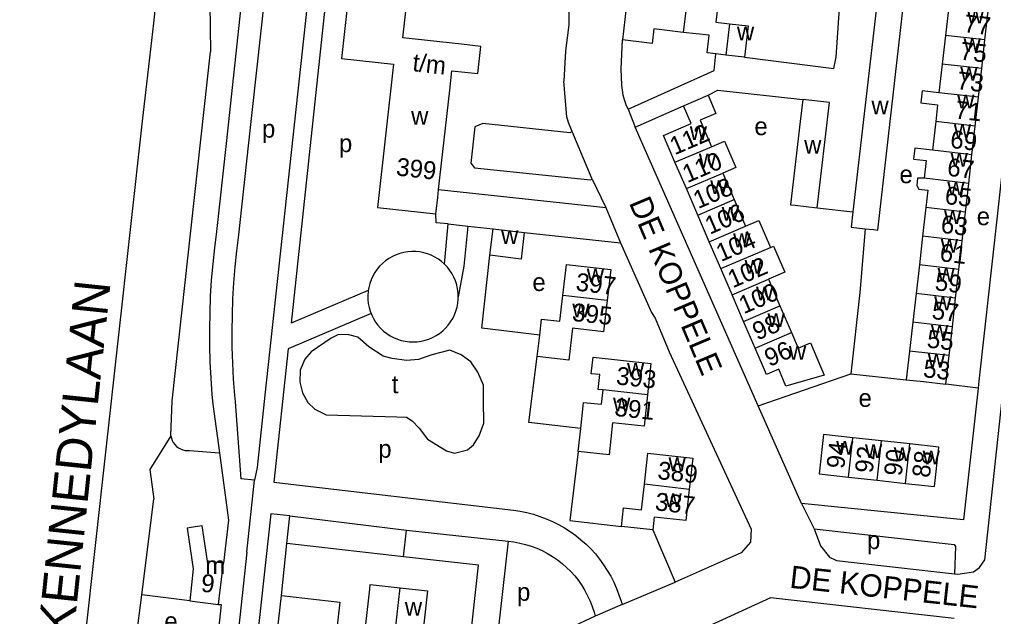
# Model space of a CAD drawing. Extents: x 161936 to 163647, y 386450 to 388633.
# Drawn here: x 162068.8 to 162286.5, y 387817.5 to 387951 of the extents above; entities that cross this region are included whole.
import ezdxf

# ---------------------------------------------------------------- set-up
doc = ezdxf.new("R2010")
doc.units = 0
for name, color, linetype in [('BLT_Basislijn', 7, 'Continuous'), ('BLT_Bebouwing', 7, 'Continuous'), ('BLT_Centroide', 7, 'Continuous'), ('BLT_Huisnummer', 7, 'Continuous'), ('BLT_Huisnummer_ tussenligend', 7, 'Continuous'), ('BLT_Huisnummer_reeks', 7, 'Continuous'), ('BLT_Onderverdeling_panden', 7, 'Continuous'), ('BLT_Straatnaam', 7, 'Continuous'), ('BLT_Straatnaam_hoofdweg', 7, 'Continuous'), ('BLT_Vlakafsluiter', 7, 'Continuous')]:
    doc.layers.add(name, color=color, linetype=linetype)

msp = doc.modelspace()

# ---------------------------------------------------------------- linework, layer by layer
at = {"layer": 'BLT_Basislijn'}
for p, q in [((162126.83, 388032.86), (162114.95, 387923.3)), ((162128.74, 388003.15), (162119.92, 387922.75)), ((162191.53, 387954.4), (162191.53, 387949.81)), ((162191.53, 387949.81), (162190.84, 387944.01)), ((162203.22, 387939.99), (162203.56, 387946.44)), ((162102.93, 387865.74), (162111.5, 387943.8)), ((162190.84, 387944.01), (162190.41, 387937.21)), ((162204.78, 387930.94), (162206.35, 387926.93)), ((162096.24, 387928.96), (162087.98, 387854.23)), ((162192.32, 387925.95), (162191.47, 387927.99)), ((162196.79, 387915.34), (162192.32, 387925.95)), ((162233.88, 387864.59), (162206.35, 387926.93)), ((162114.95, 387923.3), (162112.8, 387903.59)), ((162119.92, 387922.75), (162117.74, 387902.85)), ((162196.79, 387915.34), (162199.8, 387908.98)), ((162162.44, 387913), (162199.8, 387908.98)), ((162199.8, 387908.98), (162203.11, 387901.11)), ((162247.09, 387908.88), (162255.03, 387907.99)), ((162163.75, 387896.31), (162164.6, 387905.29)), ((162164.6, 387905.29), (162168.97, 387904.82)), ((162168.97, 387904.82), (162174.62, 387904.21)), ((162181.6, 387903.36), (162203.11, 387901.11)), ((162146.73, 387890.41), (162129.46, 387883.07)), ((162147.37, 387885.25), (162128.85, 387877.38)), ((162233.88, 387864.59), (162254.59, 387871.78)), ((162254.59, 387871.78), (162266.98, 387870.47)), ((162283.04, 387868.59), (162275.81, 387869.47)), ((162102.63, 387857.93), (162102.93, 387865.74)), ((162111.98, 387865.02), (162113.47, 387854.09)), ((162116.96, 387865.48), (162118.26, 387848.26)), ((162243.57, 387842.75), (162233.88, 387864.59)), ((162087.98, 387854.23), (162079.71, 387778.65)), ((162106.76, 387854.65), (162113.47, 387854.09)), ((162097.94, 387850.35), (162098.81, 387843.78)), ((162121.3, 387847.99), (162118.26, 387848.26)), ((162119.61, 387831.87), (162121.3, 387847.99)), ((162096.12, 387822.38), (162098.81, 387843.78)), ((162243.57, 387842.75), (162246.4, 387837.14)), ((162128.56, 387833.82), (162129.22, 387840.05)), ((162129.22, 387840.05), (162155.27, 387836.85)), ((162210.32, 387836.86), (162215.32, 387825.2)), ((162127.32, 387822.18), (162128.56, 387833.82)), ((162154.6, 387830.84), (162128.56, 387833.82)), ((162119.61, 387831.87), (162116.25, 387801.31)), ((162203.44, 387820.16), (162215.32, 387825.2)), ((162094.34, 387808.2), (162096.12, 387822.38)), ((162106.85, 387821.03), (162096.12, 387822.38)), ((162113.85, 387820.16), (162112.26, 387805.95)), ((162113.27, 387820.22), (162113.85, 387820.16)), ((162203.44, 387820.16), (162197.42, 387817.55))]:
    msp.add_line(p, q, dxfattribs=at)
for points in [[(162118.49, 388036.48), (162111.07, 387970.73), (162111.5, 387943.8)], [(162106.41, 388028.03), (162105.03, 388012.45), (162103.57, 387996.88), (162102.02, 387981.32), (162100.4, 387965.76), (162098.7, 387950.21), (162096.92, 387934.67), (162096.24, 387928.96)], [(162128.74, 388003.15), (162137.41, 388002.59), (162138.21, 388001.69), (162123.63, 387867.04)], [(162147.41, 388001.2), (162142.14, 388001.69), (162129.46, 387883.07)], [(162277.73, 387827.08), (162278.49, 387826.95), (162282, 387827.52), (162283.32, 387828.45), (162284.5, 387830.2), (162299.98, 387972.98), (162299.82, 387975.12), (162297.88, 387978.05), (162295.24, 387978.68)], [(162230.8, 387942.6), (162250.79, 387940.04), (162251.3, 387942.58), (162252.07, 387953.52)], [(162292.27, 387952.1), (162283.13, 387869.44), (162283.04, 387868.59)], [(162204.78, 387930.94), (162224.01, 387939.65), (162224.42, 387943.34)], [(162204.78, 387930.94), (162204.35, 387931.97), (162204, 387933.03), (162203.72, 387934.11), (162203.52, 387935.21), (162203.4, 387936.32), (162203.22, 387939.99)], [(162191.47, 387927.99), (162191.1, 387929.24), (162190.41, 387937.21)], [(162222.7, 387934.07), (162224.88, 387935.22), (162243.85, 387933.15)], [(162206.35, 387926.93), (162217.18, 387931.7)], [(162192.32, 387925.95), (162191.77, 387925.71), (162172.35, 387927.79), (162170.55, 387927.03), (162169.65, 387918.86), (162170.5, 387917.81), (162196.42, 387915.13), (162196.79, 387915.34)], [(162164.6, 387905.29), (162161.87, 387905.58), (162161.83, 387907.55)], [(162168.97, 387904.82), (162168.08, 387895.89), (162166.85, 387889.02)], [(162257.77, 387904.23), (162256.6, 387890), (162254.59, 387871.78)], [(162112.8, 387903.59), (162112.34, 387899.97), (162111.96, 387896.34), (162111.65, 387892.7), (162111.43, 387889.05), (162111.29, 387885.41), (162111.23, 387881.75), (162111.25, 387878.1), (162111.35, 387874.45), (162111.53, 387870.8), (162111.79, 387867.16), (162111.98, 387865.02)], [(162117.74, 387902.85), (162117.29, 387899.29), (162116.92, 387895.71), (162116.63, 387892.12), (162116.41, 387888.53), (162116.28, 387884.94), (162116.23, 387881.34), (162116.26, 387877.74), (162116.37, 387874.15), (162116.55, 387870.56), (162116.82, 387866.97), (162116.96, 387865.48)], [(162203.11, 387901.11), (162210.02, 387885.52), (162210.87, 387884.19), (162213.99, 387876.67), (162232.29, 387837.04), (162232.13, 387834.11), (162230.06, 387831.72), (162215.32, 387825.2)], [(162163.75, 387896.31), (162163.11, 387896.88), (162162.39, 387897.41), (162161.62, 387897.88), (162160.81, 387898.28), (162159.97, 387898.61), (162159.11, 387898.86), (162158.23, 387899.03), (162157.33, 387899.12), (162156.43, 387899.13), (162155.54, 387899.07), (162154.65, 387898.92), (162153.78, 387898.69), (162152.93, 387898.39), (162152.11, 387898.02), (162151.33, 387897.57), (162150.6, 387897.06), (162149.91, 387896.48), (162149.27, 387895.84), (162148.69, 387895.15), (162148.18, 387894.41), (162147.74, 387893.63), (162147.36, 387892.82), (162147.06, 387891.97), (162146.84, 387891.1), (162146.73, 387890.41)], [(162185.06, 387880.4), (162172.09, 387881.96), (162173.9, 387898.28)], [(162166.85, 387889.02), (162166.81, 387889.92), (162166.69, 387890.81), (162166.49, 387891.69), (162166.22, 387892.55), (162165.87, 387893.37), (162165.45, 387894.17), (162164.96, 387894.92), (162164.4, 387895.63), (162163.75, 387896.31)], [(162146.73, 387890.41), (162146.7, 387890.21), (162146.63, 387889.31), (162146.64, 387888.41), (162146.74, 387887.52), (162146.91, 387886.64), (162147.16, 387885.77), (162147.37, 387885.25)], [(162147.37, 387885.25), (162147.49, 387884.93), (162147.89, 387884.13), (162148.36, 387883.36), (162148.89, 387882.64), (162149.49, 387881.97), (162150.15, 387881.35), (162150.86, 387880.8), (162151.61, 387880.31), (162152.4, 387879.89), (162153.23, 387879.54), (162154.09, 387879.26), (162154.97, 387879.07), (162155.86, 387878.95), (162156.76, 387878.91), (162157.65, 387878.95), (162158.55, 387879.07), (162159.42, 387879.27), (162160.28, 387879.55), (162161.11, 387879.9), (162161.9, 387880.32), (162162.65, 387880.82), (162163.36, 387881.37), (162164.01, 387881.99), (162164.61, 387882.67), (162165.14, 387883.39), (162165.61, 387884.16), (162166, 387884.97), (162166.33, 387885.8), (162166.58, 387886.67), (162166.74, 387887.55), (162166.84, 387888.45), (162166.85, 387889.02)], [(162128.85, 387877.38), (162125.66, 387847.58), (162179.21, 387841.26)], [(162194.22, 387859.54), (162182.61, 387860.91), (162184.49, 387875.64)], [(162123.63, 387867.04), (162121.92, 387850.83), (162121.3, 387847.99)], [(162283.04, 387868.59), (162279.75, 387839.13), (162243.57, 387842.75)], [(162102.63, 387857.93), (162102.73, 387857.39), (162102.91, 387856.88), (162103.16, 387856.39), (162103.48, 387855.95), (162103.85, 387855.56), (162104.29, 387855.23), (162104.76, 387854.97), (162105.27, 387854.77), (162105.81, 387854.66), (162106.35, 387854.62), (162106.76, 387854.65)], [(162113.47, 387854.09), (162115.52, 387839.07), (162114.34, 387829.46)], [(162193.67, 387854.43), (162191.8, 387839.01), (162203.31, 387837.65)], [(162179.21, 387841.26), (162180.71, 387841.04), (162182.19, 387840.74), (162183.66, 387840.36), (162185.1, 387839.9), (162186.52, 387839.37), (162187.91, 387838.76), (162189.26, 387838.08), (162190.58, 387837.33), (162191.85, 387836.52), (162193.08, 387835.63), (162194.26, 387834.68), (162195.39, 387833.68), (162196.46, 387832.61), (162197.48, 387831.49), (162198.44, 387830.31), (162199.33, 387829.09), (162200.15, 387827.82), (162200.91, 387826.51), (162201.6, 387825.16), (162202.22, 387823.78), (162202.76, 387822.37), (162203.23, 387820.93), (162203.44, 387820.16)], [(162129.22, 387840.05), (162124.98, 387840.43), (162111.62, 387718.53)], [(162246.4, 387837.14), (162247.83, 387833.3), (162249.81, 387830.75), (162251.36, 387830.05), (162277.73, 387827.08)], [(162246.4, 387837.14), (162277.65, 387833.63), (162278, 387833.19), (162277.73, 387827.08)], [(162177.97, 387834.33), (162179.29, 387834.17), (162180.59, 387833.94), (162181.88, 387833.63), (162183.15, 387833.24), (162184.39, 387832.77), (162185.6, 387832.23), (162186.78, 387831.62), (162187.91, 387830.94), (162189.01, 387830.19), (162190.05, 387829.38), (162191.05, 387828.5), (162191.99, 387827.57), (162192.87, 387826.58), (162193.7, 387825.54), (162194.45, 387824.45), (162195.14, 387823.32), (162195.76, 387822.15), (162196.31, 387820.95), (162196.79, 387819.71), (162197.19, 387818.44), (162197.42, 387817.55)], [(162173.46, 387793.42), (162145.03, 387796.5), (162144.11, 387797.49), (162147.05, 387823.63), (162147.16, 387824.69), (162153.83, 387823.94)], [(162277.67, 387817.03), (162236.65, 387821.68), (162194.65, 387802.43), (162190.57, 387799.23), (162189.04, 387797.32), (162187.24, 387793.74), (162185.17, 387773.27), (162186.7, 387769.43)], [(162197.42, 387817.55), (162185.65, 387812.09), (162181, 387808.08), (162178.67, 387805.4), (162177.72, 387804.96), (162174.66, 387804.5)]]:
    msp.add_lwpolyline(points, dxfattribs=at)
msp.add_lwpolyline([(162152.1, 387875.17), (162150.08, 387875.73), (162146.83, 387877.84), (162144.42, 387879.95), (162142.37, 387880.51), (162140.1, 387880.55), (162138.43, 387879.73), (162133.99, 387876.69), (162132.52, 387875.03), (162131.5, 387872.59), (162131.41, 387869.89), (162132.05, 387867.49), (162133.21, 387865.39), (162134.75, 387863.85), (162137.31, 387862.63), (162153.09, 387862.16), (162155.3, 387862.09), (162156.53, 387861.24), (162158.08, 387859.64), (162159.99, 387857.13), (162164.21, 387854.58), (162165.97, 387854.05), (162168.9, 387854.81), (162170.25, 387855.88), (162171.49, 387857.88), (162172.53, 387860.77), (162172.49, 387865.73), (162172.46, 387869.24), (162171.21, 387872.13), (162169.62, 387874.43), (162167.47, 387876.02), (162164.99, 387877.05), (162160.96, 387876.06), (162157.98, 387874.97), (162155.24, 387874.75)], close=True, dxfattribs=at)
at = {"layer": 'BLT_Bebouwing'}
for p, q in [((162260.53, 387955.78), (162255.03, 387907.99)), ((162276.46, 387953.86), (162275.73, 387947.45)), ((162204.38, 387953.62), (162203.56, 387946.44)), ((162284.56, 387946.45), (162285.29, 387952.86)), ((162275.73, 387947.45), (162275, 387941.03)), ((162283.83, 387940.03), (162284.56, 387946.45)), ((162226.64, 387943.08), (162224.42, 387943.34)), ((162230.8, 387942.6), (162226.64, 387943.08)), ((162275, 387941.03), (162274.27, 387934.62)), ((162283.1, 387933.62), (162283.83, 387940.03)), ((162162.44, 387913), (162164.92, 387935.18)), ((162217.18, 387931.7), (162222.7, 387934.07)), ((162282.37, 387927.2), (162283.1, 387933.62)), ((162273.55, 387928.2), (162272.82, 387921.83)), ((162281.64, 387920.79), (162282.37, 387927.2)), ((162217.83, 387913.2), (162215.27, 387919.14)), ((162280.92, 387914.37), (162281.64, 387920.79)), ((162225.96, 387916.66), (162228.5, 387910.75)), ((162162.24, 387911.22), (162162.44, 387913)), ((162220.38, 387907.26), (162217.83, 387913.2)), ((162280.19, 387907.96), (162280.92, 387914.37)), ((162161.83, 387907.55), (162162.24, 387911.22)), ((162228.5, 387910.75), (162231.07, 387904.78)), ((162271.36, 387908.96), (162270.63, 387902.54)), ((162222.94, 387901.31), (162220.38, 387907.26)), ((162279.46, 387901.54), (162280.19, 387907.96)), ((162173.9, 387898.28), (162174.62, 387904.21)), ((162174.62, 387904.21), (162181.6, 387903.36)), ((162270.63, 387902.54), (162269.9, 387896.13)), ((162225.49, 387895.37), (162222.94, 387901.31)), ((162278.73, 387895.12), (162279.46, 387901.54)), ((162228.05, 387889.43), (162225.49, 387895.37)), ((162269.9, 387896.13), (162269.17, 387889.71)), ((162278, 387888.71), (162278.73, 387895.12)), ((162236.17, 387892.92), (162238.72, 387886.98)), ((162230.6, 387883.49), (162228.05, 387889.43)), ((162269.17, 387889.71), (162268.44, 387883.3)), ((162277.27, 387882.3), (162278, 387888.71)), ((162238.72, 387886.98), (162241.28, 387881.04)), ((162233.16, 387877.55), (162230.6, 387883.49)), ((162268.44, 387883.3), (162267.71, 387876.88)), ((162276.54, 387875.88), (162277.27, 387882.3)), ((162184.49, 387875.64), (162185.06, 387880.4)), ((162267.71, 387876.88), (162266.98, 387870.47)), ((162275.81, 387869.47), (162276.54, 387875.88)), ((162193.67, 387854.43), (162194.22, 387859.54)), ((162261.41, 387856.79), (162255.04, 387857.48)), ((162267.78, 387856.1), (162261.41, 387856.79)), ((162254.06, 387848.67), (162260.43, 387847.98)), ((162260.43, 387847.98), (162266.79, 387847.28)), ((162154.6, 387830.84), (162155.27, 387836.85)), ((162155.27, 387836.85), (162177.97, 387834.33)), ((162210.32, 387836.86), (162203.31, 387837.65)), ((162177.97, 387834.33), (162174.66, 387804.5)), ((162114.34, 387829.46), (162110.83, 387829.87)), ((162113.43, 387821.55), (162114.34, 387829.46)), ((162113.27, 387820.22), (162113.43, 387821.55))]:
    msp.add_line(p, q, dxfattribs=at)
for points in [[(162145.31, 387983.32), (162140.73, 387942.29), (162152.34, 387941), (162148.77, 387909.01), (162161.83, 387907.55)], [(162167.58, 387945.48), (162154.48, 387946.94), (162158.37, 387981.86), (162145.31, 387983.32)], [(162218.29, 387958.17), (162225.2, 387957.38), (162224.4, 387950.41), (162227.44, 387950.06)], [(162257.77, 387904.23), (162259.61, 387904.02), (162260.61, 387903.91), (162266.39, 387955.11)], [(162227.44, 387950.06), (162231.6, 387949.58), (162230.8, 387942.6)], [(162217.14, 387948.15), (162210.57, 387948.9), (162210.2, 387945.68), (162203.56, 387946.44)], [(162224.42, 387943.34), (162222.49, 387943.56), (162222.94, 387947.48), (162217.14, 387948.15)], [(162164.92, 387935.18), (162165.41, 387939.57), (162171.19, 387938.92), (162171.87, 387945), (162167.58, 387945.48)], [(162274.27, 387934.62), (162270.5, 387935.05), (162270.19, 387932.36), (162273.97, 387931.94), (162273.55, 387928.2)], [(162222.7, 387934.07), (162224.43, 387930.03), (162220.87, 387928.5), (162222.81, 387923.98), (162223.43, 387922.55)], [(162243.85, 387933.15), (162243.27, 387928.18), (162241.13, 387909.57), (162242.12, 387909.46), (162247.09, 387908.88)], [(162247.09, 387908.88), (162249.81, 387932.46), (162243.85, 387933.15)], [(162215.27, 387919.14), (162212.72, 387925.08), (162218.89, 387927.73), (162217.18, 387931.7)], [(162223.43, 387922.55), (162226.36, 387923.78), (162228.89, 387917.92), (162225.96, 387916.66)], [(162272.82, 387921.83), (162268.9, 387922.27), (162268.61, 387919.76), (162271.4, 387919.45), (162270.96, 387915.5)], [(162270.96, 387915.5), (162269.5, 387915.55), (162269.31, 387913.89), (162269.79, 387913.09), (162271.8, 387912.86), (162271.36, 387908.96)], [(162231.07, 387904.78), (162233.98, 387906.07), (162236.59, 387900)], [(162255.03, 387907.99), (162254.64, 387904.58), (162257.77, 387904.23)], [(162181.6, 387903.36), (162180.87, 387897.43), (162173.9, 387898.28)], [(162236.59, 387900), (162237.32, 387900.35), (162239.85, 387894.48), (162236.17, 387892.92)], [(162190.2, 387889.31), (162191.02, 387896.26), (162200.93, 387895.09), (162200.11, 387888.15)], [(162185.06, 387880.4), (162185.48, 387884.01), (162189.52, 387883.53), (162190.2, 387889.31)], [(162200.11, 387888.15), (162199.3, 387881.2), (162192.38, 387882.01), (162191.54, 387874.81), (162184.49, 387875.64)], [(162241.28, 387881.04), (162242.8, 387877.51)], [(162242.8, 387877.51), (162245.54, 387878.69), (162248.63, 387871.45), (162240.07, 387869.03), (162238.45, 387872.79)], [(162199.22, 387868.17), (162198.1, 387868.29), (162198.46, 387871.59), (162196.58, 387871.79), (162196.98, 387875.51), (162209.89, 387874.12), (162209.14, 387867.1)], [(162238.45, 387872.79), (162235.71, 387871.61), (162233.16, 387877.55)], [(162266.98, 387870.47), (162270.84, 387870.03), (162275.81, 387869.47)], [(162209.14, 387867.1), (162208.39, 387860.08), (162201.34, 387860.84), (162200.57, 387853.69), (162193.67, 387854.43)], [(162194.22, 387859.54), (162194.85, 387865.39), (162198.87, 387864.96), (162199.22, 387868.17)], [(162255.04, 387857.48), (162248.46, 387858.22), (162247.48, 387849.39), (162254.06, 387848.67)], [(162266.79, 387847.28), (162273.29, 387846.56), (162274.28, 387855.39), (162267.78, 387856.1)], [(162208.43, 387847.07), (162209.21, 387854.04), (162219.25, 387852.91), (162218.47, 387845.93)], [(162203.31, 387837.65), (162203.78, 387841.84), (162207.79, 387841.39), (162208.43, 387847.07)], [(162218.47, 387845.93), (162217.68, 387838.96), (162210.65, 387839.75), (162210.32, 387836.86)], [(162110.83, 387829.87), (162109.61, 387837.79), (162108.07, 387837.55), (162106.24, 387837.28)], [(162106.24, 387837.28), (162107.61, 387828.19), (162106.85, 387821.03)], [(162153.83, 387823.94), (162159.96, 387823.26), (162158.09, 387806.37), (162168.75, 387805.18), (162171.39, 387828.97), (162154.6, 387830.84)], [(162173.99, 387798.45), (162151.27, 387800.97), (162153.83, 387823.94)], [(162106.85, 387821.03), (162113.27, 387820.22)], [(162143.74, 387746.25), (162130.74, 387747.73), (162130.99, 387750), (162134.38, 387779.68), (162122.62, 387781.02), (162127.32, 387822.18)], [(162127.32, 387822.18), (162140.37, 387820.69), (162136.39, 387785.82), (162149.33, 387784.35)]]:
    msp.add_lwpolyline(points, dxfattribs=at)
at = {"layer": 'BLT_Onderverdeling_panden'}
for p, q in [((162218.29, 387958.17), (162217.14, 387948.15)), ((162227.44, 387950.06), (162226.64, 387943.08)), ((162284.56, 387946.45), (162275.73, 387947.45)), ((162283.83, 387940.03), (162275, 387941.03)), ((162283.1, 387933.62), (162274.27, 387934.62)), ((162282.37, 387927.2), (162273.55, 387928.2)), ((162215.27, 387919.14), (162223.43, 387922.55)), ((162281.64, 387920.79), (162272.82, 387921.83)), ((162217.83, 387913.2), (162225.96, 387916.66)), ((162280.92, 387914.37), (162270.96, 387915.5)), ((162220.38, 387907.26), (162228.5, 387910.75)), ((162280.19, 387907.96), (162271.36, 387908.96)), ((162222.94, 387901.31), (162231.07, 387904.78)), ((162279.46, 387901.54), (162270.63, 387902.54)), ((162225.49, 387895.37), (162236.59, 387900)), ((162278.73, 387895.12), (162269.9, 387896.13)), ((162228.05, 387889.43), (162236.17, 387892.92)), ((162200.11, 387888.15), (162190.2, 387889.31)), ((162278, 387888.71), (162269.17, 387889.71)), ((162230.6, 387883.49), (162238.72, 387886.98)), ((162277.27, 387882.3), (162268.44, 387883.3)), ((162233.16, 387877.55), (162241.28, 387881.04)), ((162276.54, 387875.88), (162267.71, 387876.88)), ((162209.14, 387867.1), (162199.22, 387868.17)), ((162254.06, 387848.67), (162255.04, 387857.48)), ((162260.43, 387847.98), (162261.41, 387856.79)), ((162266.79, 387847.28), (162267.78, 387856.1)), ((162218.47, 387845.93), (162208.43, 387847.07))]:
    msp.add_line(p, q, dxfattribs=at)
at = {"layer": 'BLT_Vlakafsluiter'}
msp.add_line((162102.63, 387857.93), (162097.94, 387850.35), dxfattribs=at)

# ---------------------------------------------------------------- texts
at = {"layer": 'BLT_Centroide'}
for s, p in [('w', (162280.52, 387950.16)), ('w', (162229.12, 387946.33)), ('w', (162279.78, 387943.75)), ('w', (162279.05, 387937.31)), ('w', (162259.18, 387929.8)), ('w', (162278.34, 387931.12)), ('w', (162156.3, 387927.47)), ('p', (162122.98, 387924.6)), ('e', (162233.03, 387925.15)), ('w', (162218.58, 387924.08)), ('w', (162277.59, 387924.5)), ('p', (162140.18, 387921.35)), ('w', (162244.14, 387921.02)), ('w', (162276.87, 387918.09)), ('w', (162220.61, 387917.91)), ('e', (162265.45, 387914.4)), ('w', (162223.16, 387911.97)), ('w', (162276.14, 387911.66)), ('w', (162225.72, 387906.03)), ('w', (162275.41, 387905.25)), ('e', (162282.72, 387905.02)), ('w', (162176.41, 387900.81)), ('w', (162228.28, 387900.09)), ('w', (162274.68, 387898.84)), ('w', (162230.83, 387894.16)), ('w', (162195.57, 387892.19)), ('w', (162273.95, 387892.41)), ('e', (162183.41, 387890.3)), ('w', (162233.39, 387888.22)), ('w', (162273.22, 387886)), ('w', (162192.33, 387884.42)), ('w', (162235.94, 387882.25)), ('w', (162272.49, 387879.59)), ('w', (162240.74, 387874.91)), ('w', (162271.77, 387873.19)), ('w', (162204.55, 387871.16)), ('t', (162151.98, 387867.44)), ('e', (162256.3, 387864.38)), ('w', (162201.43, 387863.37)), ('p', (162148.97, 387853.01)), ('w', (162251.3, 387853.69)), ('w', (162257.73, 387852.97)), ('w', (162264.17, 387852.25)), ('w', (162270.61, 387851.53)), ('w', (162213.84, 387850)), ('w', (162212.94, 387841.97)), ('p', (162258.2, 387832.59)), ('m', (162110.28, 387826.98)), ('p', (162179.98, 387821.01)), ('w', (162154.9, 387817.66)), ('e', (162101.16, 387814.47))]:
    msp.add_text(s, height=4, dxfattribs=at).set_placement(p)
at = {"layer": 'BLT_Huisnummer'}
for s, rotation, p in [('77', 353.5182, (162279.7, 387948.19)), ('73', 353.5175, (162278.14, 387935.44)), ('112', 23.2726, (162215.2, 387920.63)), ('69', 353.5161, (162276.65, 387922.33)), ('108', 23.2693, (162220.45, 387908.6)), ('65', 353.5146, (162275.44, 387909.79)), ('104', 23.2718, (162225.56, 387896.76)), ('61', 353.5139, (162274.31, 387896.99)), ('397', 353.3022, (162192.97, 387890.42)), ('100', 23.2744, (162230.64, 387885.08)), ('395', 353.8785, (162192.15, 387883.63)), ('57', 353.5188, (162272.53, 387884.07)), ('96', 23.2738, (162236.36, 387873.28)), ('393', 353.8785, (162201.99, 387869.42)), ('53', 353.5246, (162270.61, 387871.06)), ('391', 353.8785, (162201.62, 387862.39)), ('94', 83.6399, (162253.09, 387850.43)), ('88', 83.6406, (162272.22, 387848.41)), ('389', 353.5776, (162211.24, 387848.26)), ('387', 353.5776, (162210.68, 387841.29)), ('9', 354.2599, (162109.22, 387823.07))]:
    msp.add_text(s, height=4, rotation=rotation, dxfattribs=at).set_placement(p)
at = {"layer": 'BLT_Huisnummer_ tussenligend'}
for s, rotation, p in [('75', 353.5175, (162278.83, 387942.07)), ('71', 353.5161, (162277.72, 387928.91)), ('110', 23.2693, (162218.02, 387914.4)), ('67', 353.5146, (162275.98, 387916.08)), ('106', 23.2718, (162223.07, 387902.87)), ('63', 353.5139, (162274.55, 387903.33)), ('102', 23.2744, (162228.17, 387890.88)), ('59', 353.5188, (162273.22, 387890.49)), ('98', 23.2738, (162233.67, 387879.19)), ('55', 353.5246, (162271.44, 387877.68)), ('92', 83.6406, (162259.44, 387849.44)), ('90', 83.6406, (162265.93, 387848.81))]:
    msp.add_text(s, height=4, rotation=rotation, dxfattribs=at).set_placement(p)
at = {"layer": 'BLT_Huisnummer_reeks'}
for s, rotation, p in [('t/m', 353.6316, (162156.49, 387939.49)), ('399', 353.629, (162152.82, 387916.16))]:
    msp.add_text(s, height=4, rotation=rotation, dxfattribs=at).set_placement(p)
at = {"layer": 'BLT_Straatnaam'}
for rotation, p in [(292.8813, (162204.92, 387910.06)), (353.7206, (162240.76, 387823.95))]:
    msp.add_text('DE KOPPELE', height=5, rotation=rotation, dxfattribs=at).set_placement(p)
at = {"layer": 'BLT_Straatnaam_hoofdweg'}
msp.add_text('JOHN F KENNEDYLAAN', height=7.9999, rotation=84.0178, dxfattribs=at).set_placement((162076.51, 387771.59))

doc.saveas('drawing.dxf')
